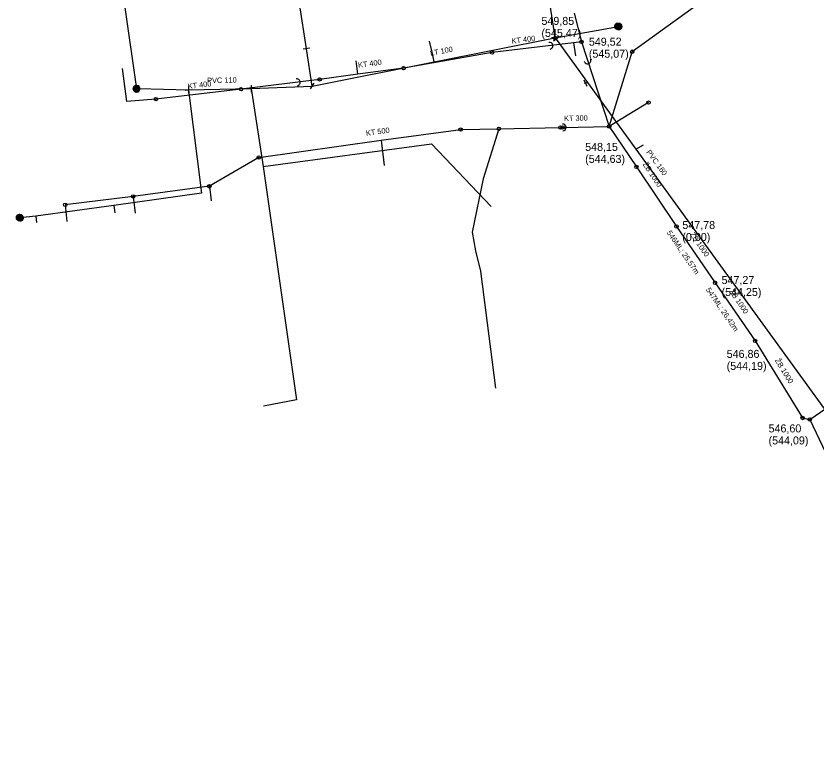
# Model space of a CAD drawing. Extents: x -867696 to -865033, y -1042522 to -1039817.
# Drawn here: x -866636.9 to -866337.2, y -1040517.5 to -1040244.3 of the extents above; entities that cross this region are included whole.
import ezdxf

# ---------------------------------------------------------------- set-up
doc = ezdxf.new("R2010")
doc.units = 0
for name, color, linetype in [('KN - destova', 7, 'Continuous'), ('KN - jednotna', 7, 'Continuous'), ('KN - ostatni', 7, 'Continuous'), ('KN - popis material', 7, 'Continuous'), ('KN - popis ostatni', 7, 'Continuous'), ('KN - popis usek delka', 7, 'Continuous'), ('KN - pripojka', 7, 'Continuous'), ('KN - sachta komora', 7, 'Continuous'), ('KN - splaskova', 7, 'Continuous'), ('Level 1', 7, 'Continuous'), ('V - armatura', 7, 'Continuous'), ('V - hydrant', 7, 'Continuous'), ('V - ostatni', 7, 'Continuous'), ('V - popis material', 7, 'Continuous'), ('V - pripojka', 7, 'Continuous'), ('V - rozvadeci', 7, 'Continuous')]:
    doc.layers.add(name, color=color, linetype=linetype)

# ---------------------------------------------------------------- blocks, each defined once
blk = doc.blocks.new('100.M')
at = {"layer": 'Level 1'}
blk.add_circle((0, 0), 1.27, dxfattribs=at)
blk = doc.blocks.new('107')
at = {"layer": 'Level 1'}
blk.add_arc((0, 0), 1.27, 270, 90, dxfattribs=at)
blk = doc.blocks.new('147')
at = {"layer": 'Level 1'}
blk.add_line((0, 1.27), (0, -1.27), dxfattribs=at)
blk = doc.blocks.new('111')
at = {"layer": 'Level 1'}
for p, q in [((0.42, 0.72), (-0.83, 0)), ((-0.83, 0), (0.42, -0.72)), ((0.42, -0.72), (0.42, 0.72))]:
    blk.add_line(p, q, dxfattribs=at)
blk = doc.blocks.new('160')
at = {"layer": 'Level 1'}
for p, q in [((-1.26, -0.04), (0.05, 1.27)), ((-1.26, -0.06), (0.06, 1.27)), ((-1.26, -0.07), (0.08, 1.27)), ((-1.26, -0.09), (0.09, 1.27)), ((-1.26, 0.11), (-0.12, 1.26)), ((-1.26, 0.1), (-0.1, 1.26)), ((-1.26, 0.08), (-0.09, 1.26)), ((-1.26, 0.07), (-0.07, 1.26)), ((-1.26, 0.06), (-0.06, 1.26)), ((-1.26, 0.04), (-0.04, 1.26)), ((-1.26, 0.03), (-0.03, 1.26)), ((-1.26, 0.01), (-0.01, 1.26)), ((-1.26, 0), (0, 1.26)), ((-1.26, -0.02), (0.02, 1.26)), ((-1.26, -0.03), (0.03, 1.26)), ((-1.26, -0.1), (0.1, 1.26)), ((-1.26, -0.11), (0.12, 1.26)), ((-1.26, -0.13), (0.13, 1.26)), ((-1.26, -0.14), (0.14, 1.26)), ((-1.26, 0.17), (-0.18, 1.25)), ((-1.26, 0.15), (-0.16, 1.25)), ((-1.26, 0.14), (-0.15, 1.25)), ((-1.26, 0.13), (-0.13, 1.25)), ((-1.26, -0.16), (0.15, 1.25)), ((-1.26, -0.17), (0.16, 1.25)), ((-1.25, 0.21), (-0.21, 1.25)), ((-1.25, 0.19), (-0.19, 1.25)), ((-1.25, -0.18), (0.17, 1.25)), ((-1.25, -0.19), (0.19, 1.25)), ((-1.25, -0.2), (0.2, 1.24)), ((-1.25, -0.21), (0.21, 1.24)), ((-1.24, 0.25), (-0.24, 1.25)), ((-1.24, 0.23), (-0.22, 1.25)), ((-1.24, -0.22), (0.22, 1.24)), ((-1.24, -0.24), (0.23, 1.24)), ((-1.24, -0.25), (0.25, 1.24)), ((-1.23, 0.27), (-0.26, 1.24)), ((-1.23, 0.29), (-0.28, 1.23)), ((-1.23, -0.26), (0.26, 1.23)), ((-1.23, -0.27), (0.27, 1.23)), ((-1.23, -0.28), (0.28, 1.23)), ((-1.23, -0.29), (0.29, 1.23)), ((-1.22, 0.3), (-0.3, 1.23)), ((-1.22, 0.32), (-0.32, 1.22)), ((-1.22, -0.3), (0.31, 1.22)), ((-1.22, -0.32), (0.32, 1.22)), ((-1.22, -0.33), (0.33, 1.22)), ((-1.21, -0.34), (0.34, 1.22)), ((-1.21, -0.35), (0.35, 1.22)), ((-1.21, 0.36), (-0.36, 1.21)), ((-1.21, 0.34), (-0.34, 1.21)), ((-1.21, -0.36), (0.36, 1.21)), ((-1.21, -0.37), (0.38, 1.21)), ((-1.2, -0.38), (0.39, 1.21)), ((-1.2, 0.38), (-0.38, 1.2)), ((-1.2, -0.39), (0.4, 1.2)), ((-1.2, -0.41), (0.41, 1.2)), ((-1.2, 0.4), (-0.4, 1.19)), ((-1.19, -0.42), (0.42, 1.2)), ((-1.19, 0.42), (-0.43, 1.19)), ((-1.19, -0.43), (0.43, 1.19)), ((-1.19, -0.44), (0.44, 1.19)), ((-1.19, 0.44), (-0.45, 1.18)), ((-1.19, -0.45), (0.45, 1.18)), ((-1.18, -0.46), (0.46, 1.18)), ((-1.18, 0.46), (-0.47, 1.17)), ((-1.18, -0.47), (0.47, 1.17)), ((-1.17, 0.48), (-0.49, 1.17)), ((-1.17, -0.48), (0.48, 1.17)), ((-1.17, -0.49), (0.49, 1.16)), ((-1.16, 0.51), (-0.51, 1.16)), ((-1.16, -0.5), (0.5, 1.16)), ((-1.16, -0.51), (0.5, 1.16)), ((-1.15, -0.52), (0.51, 1.15)), ((-1.15, -0.53), (0.52, 1.15)), ((-1.14, 0.54), (-0.53, 1.15)), ((-1.14, -0.54), (0.53, 1.14)), ((-1.14, -0.54), (0.54, 1.14)), ((-1.13, -0.55), (0.55, 1.13)), ((-1.13, -0.56), (0.56, 1.13)), ((-1.12, 0.58), (-0.56, 1.14)), ((-1.12, -0.57), (0.57, 1.12)), ((-1.12, -0.58), (0.58, 1.12)), ((-1.11, -0.59), (0.59, 1.11)), ((-1.11, -0.6), (0.6, 1.11)), ((-1.1, 0.61), (-0.6, 1.11)), ((-1.1, -0.61), (0.61, 1.11)), ((-1.1, -0.62), (0.62, 1.1)), ((-1.09, -0.63), (0.63, 1.1)), ((-1.09, 0.64), (-0.64, 1.09)), ((-1.09, -0.64), (0.64, 1.09)), ((-1.08, -0.65), (0.65, 1.09)), ((-1.08, -0.65), (0.66, 1.08)), ((-1.07, -0.66), (0.67, 1.08)), ((-1.07, -0.67), (0.68, 1.07)), ((-1.07, 0.67), (-0.68, 1.06)), ((-1.06, -0.68), (0.69, 1.07)), ((-1.06, -0.69), (0.69, 1.06)), ((-1.05, -0.7), (0.7, 1.05)), ((-1.05, -0.71), (0.71, 1.05)), ((-1.05, 0.7), (-0.71, 1.04)), ((-1.04, -0.72), (0.72, 1.04)), ((-1.04, -0.73), (0.72, 1.04)), ((-1.03, -0.74), (0.73, 1.03)), ((-1.03, -0.75), (0.74, 1.02)), ((-1.03, 0.73), (-0.75, 1.01)), ((-1.02, -0.75), (0.75, 1.02)), ((-1.01, -0.76), (0.76, 1.01)), ((-1.01, -0.77), (0.76, 1)), ((-1, -0.77), (0.77, 1)), ((-0.99, -0.78), (0.78, 0.99)), ((-0.99, -0.79), (0.79, 0.98)), ((-0.98, -0.8), (0.79, 0.98)), ((-0.97, -0.8), (0.8, 0.97)), ((-0.97, -0.81), (0.81, 0.97)), ((-0.96, -0.82), (0.82, 0.96)), ((-0.95, -0.83), (0.83, 0.95)), ((-0.95, -0.83), (0.83, 0.95)), ((-0.94, -0.84), (0.84, 0.94)), ((-0.93, -0.85), (0.85, 0.93)), ((-0.93, -0.86), (0.86, 0.93)), ((-0.92, -0.86), (0.86, 0.92)), ((-0.91, 0.87), (-0.79, 0.99)), ((-0.91, -0.87), (0.87, 0.91)), ((-0.91, -0.88), (0.88, 0.91)), ((-0.9, -0.88), (0.89, 0.9)), ((-0.89, -0.89), (0.89, 0.89)), ((-0.88, -0.9), (0.9, 0.89)), ((-0.88, -0.91), (0.91, 0.88)), ((-0.87, -0.91), (0.92, 0.88)), ((-0.86, -0.92), (0.93, 0.87)), ((-0.86, -0.93), (0.93, 0.86)), ((-0.85, -0.94), (0.94, 0.85)), ((-0.84, -0.94), (0.94, 0.84)), ((-0.84, -0.95), (0.95, 0.84)), ((-0.83, -0.96), (0.96, 0.83)), ((-0.82, -0.96), (0.96, 0.82)), ((-0.82, -0.97), (0.97, 0.81)), ((-0.81, -0.98), (0.97, 0.8)), ((-0.8, -0.98), (0.98, 0.8)), ((-0.79, -0.99), (0.99, 0.79)), ((-0.78, -1), (0.99, 0.78)), ((-0.77, -1), (1, 0.77)), ((-0.77, -1.01), (1, 0.76)), ((-0.76, -1.01), (1.01, 0.75)), ((-0.75, -1.02), (1.02, 0.75)), ((-0.74, -1.02), (1.02, 0.74)), ((-0.73, -1.03), (1.03, 0.73)), ((-0.72, -1.03), (1.03, 0.72)), ((-0.71, -1.04), (1.04, 0.71)), ((-0.71, -1.04), (1.04, 0.71)), ((-0.7, -1.05), (1.05, 0.7)), ((-0.69, -1.06), (1.06, 0.69)), ((-0.68, -1.06), (1.06, 0.68)), ((-0.67, -1.07), (1.07, 0.67)), ((-0.66, -1.07), (1.07, 0.66)), ((-0.65, -1.08), (1.08, 0.66)), ((-0.64, -1.08), (1.09, 0.65)), ((-0.64, -1.09), (1.09, 0.64)), ((-0.63, -1.09), (1.1, 0.63)), ((-0.62, -1.1), (1.1, 0.62)), ((-0.61, -1.11), (1.11, 0.62)), ((-0.6, -1.11), (1.12, 0.61)), ((-0.59, -1.12), (1.12, 0.6)), ((-0.58, -1.12), (1.12, 0.59)), ((-0.58, -1.13), (1.13, 0.58)), ((-0.57, -1.13), (1.13, 0.57)), ((-0.56, -1.14), (1.14, 0.56)), ((-0.55, -1.14), (1.14, 0.55)), ((-0.54, -1.15), (1.14, 0.54)), ((-0.53, -1.15), (1.15, 0.52)), ((-0.52, -1.16), (1.15, 0.51)), ((-0.51, -1.16), (1.16, 0.5)), ((-0.5, -1.16), (1.16, 0.49)), ((-0.49, -1.17), (1.16, 0.48)), ((-0.48, -1.17), (1.17, 0.47)), ((-0.47, -1.17), (1.17, 0.46)), ((-0.46, -1.18), (1.18, 0.45)), ((-0.44, -1.18), (1.18, 0.44)), ((-0.43, -1.18), (1.18, 0.43)), ((-0.42, -1.19), (1.19, 0.42)), ((-0.41, -1.19), (1.19, 0.41)), ((-0.4, -1.19), (1.2, 0.4)), ((-0.39, -1.2), (1.2, 0.39)), ((-0.38, -1.2), (1.2, 0.38)), ((-0.37, -1.2), (1.21, 0.37)), ((-0.36, -1.21), (1.21, 0.36)), ((-0.35, -1.21), (1.22, 0.35)), ((-0.34, -1.22), (1.22, 0.34)), ((-0.33, -1.22), (1.22, 0.33)), ((-0.32, -1.22), (1.23, 0.32)), ((-0.31, -1.23), (1.23, 0.31)), ((-0.3, -1.23), (1.23, 0.3)), ((-0.28, -1.23), (1.23, 0.29)), ((-0.27, -1.24), (1.24, 0.27)), ((-0.26, -1.24), (1.24, 0.26)), ((-0.25, -1.24), (1.24, 0.25)), ((-0.24, -1.25), (1.24, 0.24)), ((-0.23, -1.25), (1.24, 0.22)), ((-0.22, -1.25), (1.24, 0.21)), ((-0.2, -1.25), (1.24, 0.2)), ((-0.19, -1.25), (1.25, 0.19)), ((-0.18, -1.25), (1.25, 0.17)), ((-0.16, -1.25), (1.25, 0.16)), ((-0.15, -1.25), (1.25, 0.15)), ((-0.14, -1.25), (1.25, 0.14)), ((-0.12, -1.25), (1.25, 0.12)), ((-0.11, -1.26), (1.26, 0.11)), ((-0.1, -1.26), (1.26, 0.1)), ((-0.08, -1.26), (1.26, 0.09)), ((-0.07, -1.26), (1.26, 0.07)), ((-0.06, -1.26), (1.26, 0.06)), ((-0.04, -1.26), (1.26, 0.05)), ((-0.03, -1.26), (1.27, 0.04)), ((-0.02, -1.26), (1.27, 0.02)), ((0, -1.26), (1.27, 0.01)), ((0.01, -1.26), (1.27, 0)), ((0.02, -1.26), (1.27, -0.02)), ((0.04, -1.27), (1.27, -0.04)), ((0.05, -1.27), (1.26, -0.05)), ((0.06, -1.27), (1.26, -0.07)), ((0.08, -1.27), (1.26, -0.08)), ((0.09, -1.26), (1.26, -0.1)), ((0.11, -1.26), (1.26, -0.12)), ((0.13, -1.26), (1.25, -0.13)), ((0.15, -1.25), (1.25, -0.15)), ((0.16, -1.25), (1.25, -0.17)), ((0.18, -1.25), (1.25, -0.18)), ((0.2, -1.24), (1.24, -0.2)), ((0.22, -1.24), (1.24, -0.21)), ((0.23, -1.24), (1.24, -0.23)), ((0.25, -1.24), (1.24, -0.25)), ((0.27, -1.23), (1.24, -0.26)), ((0.28, -1.23), (1.23, -0.28)), ((0.3, -1.23), (1.23, -0.3)), ((0.32, -1.22), (1.23, -0.31)), ((0.34, -1.22), (1.22, -0.33)), ((0.35, -1.22), (1.22, -0.35)), ((0.37, -1.21), (1.21, -0.38)), ((0.39, -1.21), (1.2, -0.4)), ((0.42, -1.2), (1.19, -0.43)), ((0.44, -1.18), (1.18, -0.45)), ((0.47, -1.17), (1.17, -0.47)), ((0.5, -1.16), (1.16, -0.5)), ((0.52, -1.15), (1.15, -0.52)), ((0.55, -1.13), (1.14, -0.54)), ((0.58, -1.12), (1.13, -0.57)), ((0.6, -1.11), (1.12, -0.59)), ((0.63, -1.1), (1.11, -0.61)), ((0.65, -1.09), (1.08, -0.66)), ((0.69, -1.06), (1.04, -0.72)), ((0.77, -1), (1, -0.77)), ((0.85, -0.93), (0.96, -0.82))]:
    blk.add_line(p, q, dxfattribs=at)
blk.add_circle((0, 0), 1.27, dxfattribs=at)
blk = doc.blocks.new('150')
at = {"layer": 'Level 1'}
blk.add_line((0, 1.27), (0, -1.27), dxfattribs=at)

msp = doc.modelspace()

# ---------------------------------------------------------------- linework, layer by layer
at = {"layer": 'KN - destova'}
for points in [[(-866376.448, -1040236.199), (-866406.008, -1040257.679)], [(-866414.658, -1040285.718), (-866406.008, -1040257.679)]]:
    msp.add_lwpolyline(points, dxfattribs=at)
at = {"layer": 'KN - jednotna'}
for points in [[(-866427.788, -1040243.249), (-866425.029, -1040254.038)], [(-866425.029, -1040254.038), (-866428.033, -1040254.392), (-866458.548, -1040257.986)], [(-866425.029, -1040254.038), (-866414.658, -1040285.718)], [(-866458.548, -1040257.986), (-866491.661, -1040263.873)], [(-866491.661, -1040263.873), (-866508.803, -1040266.17), (-866523.114, -1040268.087)], [(-866523.114, -1040268.087), (-866552.573, -1040271.772)], [(-866552.573, -1040271.772), (-866584.442, -1040275.461)], [(-866399.907, -1040276.771), (-866414.658, -1040285.718)], [(-866432.093, -1040286.077), (-866414.658, -1040285.718)], [(-866414.658, -1040285.718), (-866404.46, -1040300.877)], [(-866545.93, -1040297.32), (-866500.013, -1040290.877), (-866470.286, -1040286.865)], [(-866470.286, -1040286.865), (-866455.977, -1040286.57)], [(-866455.977, -1040286.57), (-866432.94, -1040286.095)], [(-866432.94, -1040286.095), (-866432.093, -1040286.077)], [(-866404.46, -1040300.877), (-866389.438, -1040323.208)], [(-866389.438, -1040323.208), (-866374.988, -1040344.299)], [(-866374.988, -1040344.299), (-866360.019, -1040366.069)], [(-866360.019, -1040366.069), (-866342.209, -1040394.957)], [(-866339.517, -1040395.518), (-866308.757, -1040374.429)], [(-866342.209, -1040394.957), (-866339.517, -1040395.518)]]:
    msp.add_lwpolyline(points, dxfattribs=at)
at = {"layer": 'KN - pripojka'}
for points in [[(-866428.033, -1040254.392), (-866427.32, -1040259.18)], [(-866508.803, -1040266.17), (-866509.473, -1040261.144)], [(-866584.442, -1040275.461), (-866595.335, -1040276.358), (-866597.017, -1040263.966)], [(-866455.977, -1040286.57), (-866461.89, -1040305.359), (-866466.033, -1040325.271), (-866464.76, -1040332.315), (-866462.856, -1040339.911), (-866457.218, -1040383.757)], [(-866500.013, -1040290.877), (-866498.915, -1040300.386)], [(-866339.517, -1040395.518), (-866324.229, -1040427.611), (-866298.12, -1040515.307), (-866296.543, -1040517.515)]]:
    msp.add_lwpolyline(points, dxfattribs=at)
at = {"layer": 'KN - splaskova'}
for points in [[(-866545.93, -1040297.32), (-866564.43, -1040308.12)], [(-866564.43, -1040308.12), (-866592.98, -1040311.91)], [(-866564.43, -1040308.12), (-866563.811, -1040313.629)], [(-866592.98, -1040311.91), (-866618.45, -1040315.07)], [(-866592.98, -1040311.91), (-866592.198, -1040318.207)], [(-866618.45, -1040315.07), (-866617.838, -1040321.361)]]:
    msp.add_lwpolyline(points, dxfattribs=at)
at = {"layer": 'V - pripojka'}
for points in [[(-866411.224, -1040248.225), (-866411.021, -1040248.21)], [(-866480.249, -1040261.489), (-866480.992, -1040257.877), (-866481.962, -1040253.785)], [(-866422.823, -1040269.186), (-866424.082, -1040269.588)], [(-866591.714, -1040271.546), (-866592.542, -1040271.567)], [(-866548.781, -1040271.536), (-866544.324, -1040300.695), (-866481.274, -1040292.255), (-866458.871, -1040315.725)], [(-866404.632, -1040294.262), (-866401.787, -1040292.537)], [(-866544.324, -1040300.695), (-866531.734, -1040388.18), (-866544.118, -1040390.58)], [(-866600.19, -1040315.34), (-866599.849, -1040318.051)], [(-866635.46, -1040319.9), (-866635.719, -1040319.92)], [(-866629.5, -1040319.36), (-866629.151, -1040321.743)]]:
    msp.add_lwpolyline(points, dxfattribs=at)
at = {"layer": 'V - rozvadeci'}
for points in [[(-866528.076, -1040256.593), (-866530.637, -1040239.583), (-866535.256, -1040208.905), (-866541.165, -1040169.659), (-866543.102, -1040157.902), (-866550.41, -1040107.62)], [(-866434.953, -1040252.287), (-866443.43, -1040197.747), (-866448.439, -1040161.838)], [(-866599.51, -1040217.35), (-866596.214, -1040240.235), (-866591.714, -1040271.546)], [(-866434.918, -1040252.514), (-866411.224, -1040248.225)], [(-866525.976, -1040270.544), (-866480.249, -1040261.489), (-866434.981, -1040252.525), (-866434.918, -1040252.514)], [(-866434.918, -1040252.514), (-866434.953, -1040252.287)], [(-866434.918, -1040252.514), (-866434.535, -1040253.041)], [(-866434.535, -1040253.041), (-866422.823, -1040269.186), (-866404.632, -1040294.262), (-866256.693, -1040498.196), (-866245.2, -1040514.039)], [(-866525.976, -1040270.544), (-866528.076, -1040256.593)], [(-866548.781, -1040271.536), (-866525.976, -1040270.544)], [(-866572.248, -1040272.105), (-866567.4, -1040310.76), (-866600.19, -1040315.34), (-866629.5, -1040319.36), (-866635.46, -1040319.9)], [(-866591.714, -1040271.546), (-866591.035, -1040271.536)], [(-866591.035, -1040271.536), (-866572.26, -1040272.01)], [(-866572.26, -1040272.01), (-866548.781, -1040271.536)], [(-866572.26, -1040272.01), (-866572.248, -1040272.105)]]:
    msp.add_lwpolyline(points, dxfattribs=at)

# ---------------------------------------------------------------- block references
at = {"layer": 'KN - ostatni'}
for p, xscale, yscale, rotation in [((-866436.98, -1040255.446), 1.0098116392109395, 1.0098116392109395, 10.610301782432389), ((-866422.767, -1040260.948), 0.999999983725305, 0.999999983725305, -70.99999877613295), ((-866531.679, -1040269.158), 1.0092050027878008, 1.0092050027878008, 11.116918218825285), ((-866432.093, -1040286.077), 1.00000001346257, 1.0000000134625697, 1.9999999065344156)]:
    msp.add_blockref('107', p, dxfattribs=dict(at, xscale=xscale, yscale=yscale, rotation=rotation))
at = {"layer": 'KN - sachta komora'}
for p, xscale, yscale, rotation in [((-866425.029, -1040254.038), 0.49999998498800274, 0.49999998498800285, 106.99999966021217), ((-866458.548, -1040257.986), 0.5041888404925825, 0.5041888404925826, -168.37362119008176), ((-866406.008, -1040257.679), 0.5000000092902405, 0.5000000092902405, -125.00000023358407), ((-866491.661, -1040263.873), 0.5041888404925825, 0.5041888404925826, -168.37362119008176), ((-866523.114, -1040268.087), 0.5046025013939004, 0.5046025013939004, 11.116918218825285), ((-866552.573, -1040271.772), 0.5049058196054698, 0.5049058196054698, -169.38969821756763), ((-866584.442, -1040275.461), 0.5049058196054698, 0.5049058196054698, -169.38969821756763), ((-866399.907, -1040276.771), 0.4999999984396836, 0.49999999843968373, -147.99999972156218), ((-866432.94, -1040286.095), 0.500000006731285, 0.5000000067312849, 1.9999999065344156), ((-866432.093, -1040286.077), 0.500000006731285, 0.5000000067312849, 1.9999999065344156), ((-866414.658, -1040285.718), 0.49999999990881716, 0.49999999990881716, 116.9999993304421), ((-866470.286, -1040286.865), 0.5009132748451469, 0.5009132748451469, 6.078126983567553), ((-866455.977, -1040286.57), 0.500000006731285, 0.5000000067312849, -178.0000000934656), ((-866545.93, -1040297.32), 0.5148474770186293, 0.5148474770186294, 24.133790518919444), ((-866404.46, -1040300.877), 0.4999999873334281, 0.499999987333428, -55.999999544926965), ((-866564.43, -1040308.12), 0.5158478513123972, 0.5158478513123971, 23.584588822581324), ((-866592.98, -1040311.91), 0.5046025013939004, 0.5046025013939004, 11.116918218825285), ((-866618.45, -1040315.07), 0.5046025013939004, 0.5046025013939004, -168.88308178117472), ((-866389.438, -1040323.208), 0.5000000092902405, 0.5000000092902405, 125.00000023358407), ((-866374.988, -1040344.299), 0.5000000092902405, 0.5000000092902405, 125.00000023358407), ((-866360.019, -1040366.069), 0.4999999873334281, 0.499999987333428, 124.00000045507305), ((-866342.209, -1040394.957), 0.5000000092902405, 0.5000000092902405, 144.99999976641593), ((-866339.517, -1040395.518), 0.5022931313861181, 0.5022931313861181, -166.82590928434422)]:
    msp.add_blockref('100.M', p, dxfattribs=dict(at, xscale=xscale, yscale=yscale, rotation=rotation))
at = {"layer": 'V - armatura'}
for p, xscale, yscale, rotation in [((-866434.953, -1040252.287), 1.0000000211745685, 1.0000000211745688, -81.00000039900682), ((-866434.535, -1040253.041), 1.000000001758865, 1.000000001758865, -54.00000066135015), ((-866528.076, -1040256.593), 1.0000000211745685, 1.0000000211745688, -81.00000039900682), ((-866548.781, -1040271.536), 1.00000001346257, 1.0000000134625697, 1.9999999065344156), ((-866525.976, -1040270.544), 1.000000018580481, 1.000000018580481, -35.000000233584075), ((-866572.248, -1040272.105), 0.9999999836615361, 0.9999999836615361, -81.99999961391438)]:
    msp.add_blockref('147', p, dxfattribs=dict(at, xscale=xscale, yscale=yscale, rotation=rotation))
for p in [(-866591.035, -1040271.536), (-866572.26, -1040272.01)]:
    msp.add_blockref('147', p, dxfattribs=at)
at = {"layer": 'V - hydrant'}
for p, xscale, yscale, rotation in [((-866411.114, -1040248.217), 1.0018265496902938, 1.0018265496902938, 6.078126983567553), ((-866592.164, -1040271.557), 1.00000001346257, 1.0000000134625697, -178.0000000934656), ((-866423.583, -1040269.429), 1.033506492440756, 1.033506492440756, 23.041281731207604)]:
    msp.add_blockref('150', p, dxfattribs=dict(at, xscale=xscale, yscale=yscale, rotation=rotation))
at = {"layer": 'V - ostatni'}
for name, p, xscale, yscale, rotation in [('160', (-866411.224, -1040248.225), 1.0060666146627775, 1.0060666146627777, 12.654735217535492), ('111', (-866434.918, -1040252.514), 1.000000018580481, 1.000000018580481, 54.99999976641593), ('160', (-866591.714, -1040271.546), 1.0000000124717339, 1.0000000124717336, -40.00000131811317), ('160', (-866635.46, -1040319.9), 1.0011217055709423, 1.0011217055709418, -173.41739016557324)]:
    msp.add_blockref(name, p, dxfattribs=dict(at, xscale=xscale, yscale=yscale, rotation=rotation))

# ---------------------------------------------------------------- texts
at = {"layer": 'KN - popis material'}
for s, rotation, p in [('KT 400', 6.72, (-866451.094, -1040254.692)), ('KT 400', 7.63, (-866508.607, -1040263.722)), ('KT 400', 6.6, (-866572.427, -1040271.653)), ('KT 300', 1.18, (-866431.561, -1040283.666)), ('KT 500', 7.69, (-866505.64, -1040289.215)), ('ŽB 1000', 303.93, (-866402.172, -1040299.979)), ('ŽB 1000', 304.42, (-866384.521, -1040326.139)), ('ŽB 1000', 304.51, (-866369.855, -1040347.528)), ('ŽB 1000', 301.65, (-866352.675, -1040373.407))]:
    msp.add_text(s, height=2, rotation=rotation, dxfattribs=at).set_placement(p)
at = {"layer": 'KN - popis ostatni'}
for s, p in [('549,85 ', (-866440.038, -1040247.649)), ('(545,47)', (-866440.038, -1040252.149)), ('549,52 ', (-866422.279, -1040255.438)), ('(545,07)', (-866422.279, -1040259.938)), ('548,15 ', (-866423.658, -1040294.868)), ('(544,63)', (-866423.658, -1040299.368)), ('547,78 ', (-866387.248, -1040324.128)), ('(0,00)', (-866387.248, -1040328.628)), ('547,27 ', (-866372.568, -1040344.749)), ('(544,25)', (-866372.568, -1040349.249)), ('546,86 ', (-866370.639, -1040372.439)), ('(544,19)', (-866370.639, -1040376.939)), ('546,60 ', (-866354.959, -1040400.367)), ('(544,09)', (-866354.959, -1040404.867))]:
    msp.add_text(s, height=3, dxfattribs=at).set_placement(p)
at = {"layer": 'KN - popis usek delka'}
for s, rotation, p in [('546ML; 25,57m', 304.42, (-866393.183, -1040325.528)), ('547ML; 26,42m', 304.51, (-866378.517, -1040346.931))]:
    msp.add_text(s, height=1.99999, rotation=rotation, dxfattribs=at).set_placement(p)
at = {"layer": 'V - popis material'}
for s, rotation, p in [('LT 100', 11.2, (-866481.538, -1040259.297)), ('PVC 110', 1.16, (-866565.244, -1040269.463)), ('PVC 160', 305.96, (-866400.863, -1040295.371))]:
    msp.add_text(s, height=2, rotation=rotation, dxfattribs=at).set_placement(p)

doc.saveas('drawing.dxf')
